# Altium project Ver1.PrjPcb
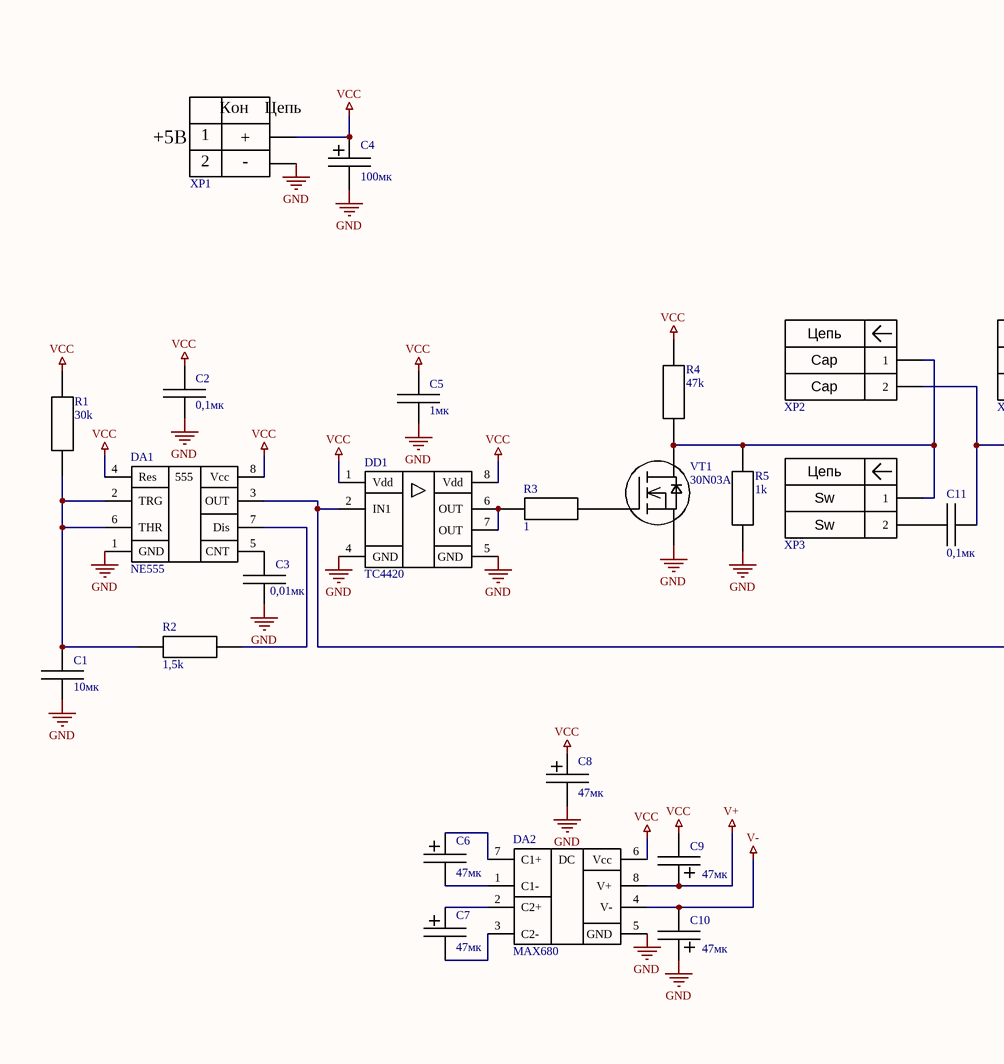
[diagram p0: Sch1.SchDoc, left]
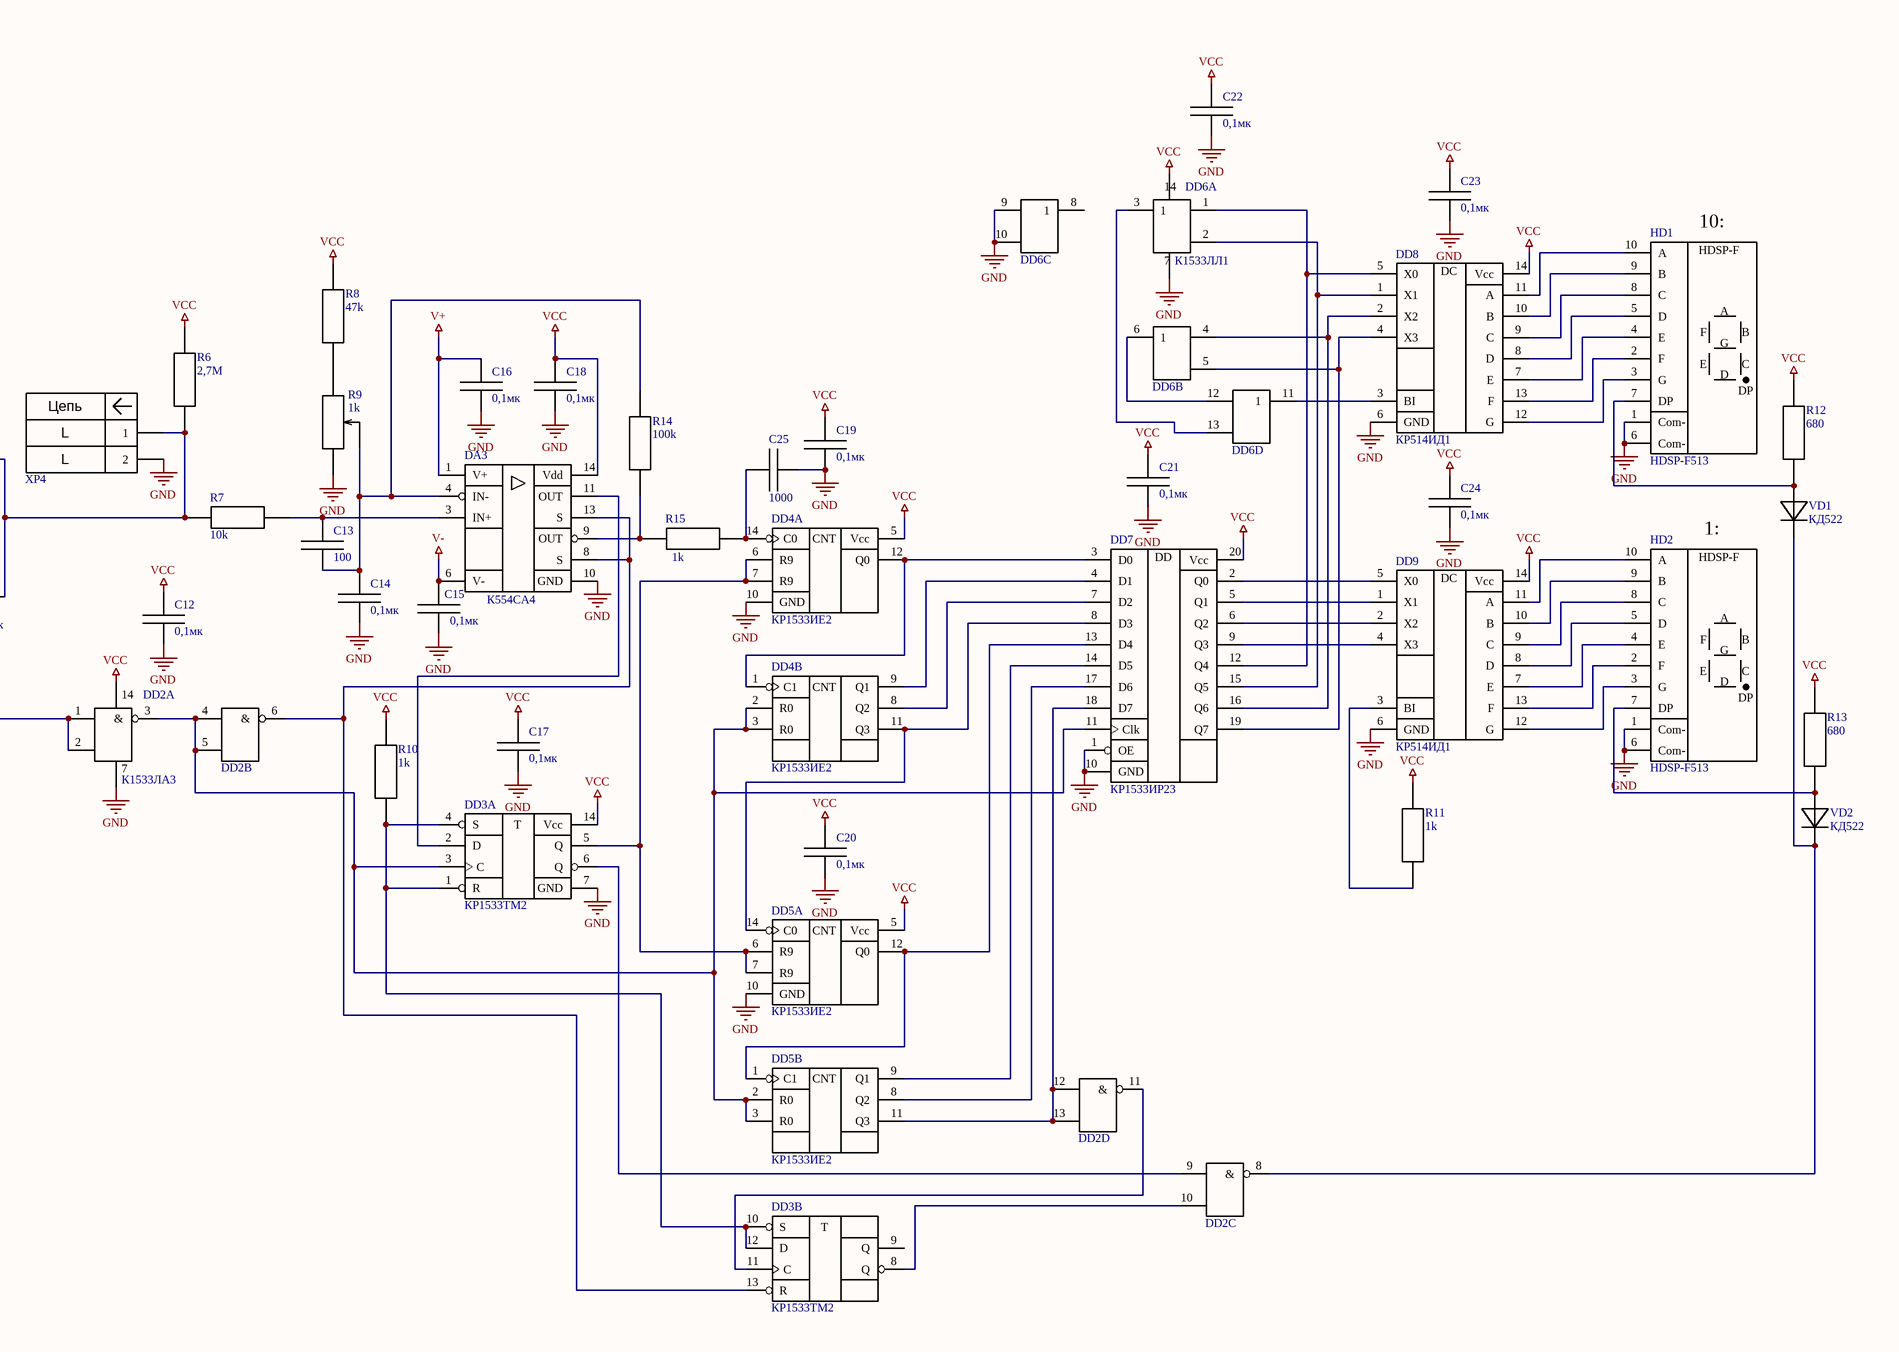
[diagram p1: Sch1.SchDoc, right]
1 sheet, 61 parts. Net scope: global (net labels, ports and power ports of the same name join across sheets).
Board file: PCB1.PcbDoc

## Sheet Sch1.SchDoc: Наименование
size 594 x 420 mm; ApprovedBy: Утвердил; CheckedBy: Проверил; Author: E.J.SanYo; CompanyName: Организация; DocumentNumber: Обозначение; SheetTotal: 1; TechContr: Техн.контр.; NormCotr: Нормоконтроль; DocumentType: Схема электрическая принципиальная; InvNumOrigin: Инв № подл; InvNumDuplicate: Инв № дубл; InsteadOfInvNum: Взам. инв. №; RefNumber: Справ. №; InitialUsage: Перв. примен.; Lit: О

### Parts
C1  value 10мк  [RC_1206]  (hidden comment: C_1206)
C2  value 0,1мк  [RC_1206]  (hidden comment: C_1206)
C3  value 0,01мк  [RC_1206]  (hidden comment: C_1206)
C4  value 100мк  [Type D]  (hidden comment: Type D)
C5  value 1мк  [RC_1206]  (hidden comment: C_1206)
C6  value 47мк  [Type C]  (hidden comment: Type C)
C7  value 47мк  [Type C]  (hidden comment: Type C)
C8  value 47мк  [Type C]  (hidden comment: Type C)
C9  value 47мк  [Type C]  (hidden comment: Type C)
C10  value 47мк  [Type C]  (hidden comment: Type C)
C11  value 0,1мк  [RC_1206]  (hidden comment: C_1206)
C12  value 0,1мк  [RC_1206]  (hidden comment: C_1206)
C13  value 100  [RC_1206]  (hidden comment: C_1206)
C14  value 0,1мк  [RC_1206]  (hidden comment: C_1206)
C15  value 0,1мк  [RC_1206]  (hidden comment: C_1206)
C16  value 0,1мк  [RC_1206]  (hidden comment: C_1206)
C17  value 0,1мк  [RC_1206]  (hidden comment: C_1206)
C18  value 0,1мк  [RC_1206]  (hidden comment: C_1206)
C19  value 0,1мк  [RC_1206]  (hidden comment: C_1206)
C20  value 0,1мк  [RC_1206]  (hidden comment: C_1206)
C21  value 0,1мк  [RC_1206]  (hidden comment: C_1206)
C22  value 0,1мк  [RC_1206]  (hidden comment: C_1206)
C23  value 0,1мк  [RC_1206]  (hidden comment: C_1206)
C24  value 0,1мк  [RC_1206]  (hidden comment: C_1206)
C25  value 1000  [RC_1206]  (hidden comment: C_1206)
DA1  NE555  [DIP-8]
DA2  MAX680  [DIP-8]
DA3  К554СА4  [DIP-14-RU]
DD1  TC4420  [DIP-8]
DD2  К1533ЛА3  [DIP-14-RU]  (parts A,B,C,D of 4)
DD3  КР1533ТМ2  [DIP-14-RU]  (parts A,B of 2)
DD4  КР1533ИЕ2  [DIP-14-RU]  (parts A,B of 2)
DD5  КР1533ИЕ2  [DIP-14-RU]  (parts A,B of 2)
DD6  К1533ЛЛ1  [DIP-14-RU]  (parts A,B,C,D of 4)
DD7  КР1533ИР23  [DIP-20-RU]
DD8  КР514ИД1  [DIP-14-RU]
DD9  КР514ИД1  [DIP-14-RU]
HD1  HDSP-F513  [HDSP-F]
HD2  HDSP-F513  [HDSP-F]
R1  value 30k  [RC_1206]  (hidden comment: R_1206)
R2  value 1,5k  [RC_1206]  (hidden comment: R_1206)
R3  value 1  [RC_1206]  (hidden comment: R_1206)
R4  value 47k  [RC_1206]  (hidden comment: R_1206)
R5  value 1k  [RC_1206]  (hidden comment: R_1206)
R6  value 2,7M  [RC_1206]  (hidden comment: R_1206)
R7  value 10k  [RC_1206]  (hidden comment: R_1206)
R8  value 47k  [RC_1206]  (hidden comment: R_1206)
R9  value 1k  [3296W]  (hidden comment: 3296)
R10  value 1k  [RC_1206]  (hidden comment: R_1206)
R11  value 1k  [RC_1206]  (hidden comment: R_1206)
R12  value 680  [RC_1206]  (hidden comment: R_1206)
R13  value 680  [RC_1206]  (hidden comment: R_1206)
R14  value 100k  [RC_1206]  (hidden comment: R_1206)
R15  value 1k  [RC_1206]  (hidden comment: R_1206)
VD1  КД522  [DO-35]
VD2  КД522  [DO-35]
VT1  30N03A  [TO-252]
XP1  Power  [2EDGV-2P]  (value not drawn)
XP2  Cap  [PLS-2]  (value not drawn)
XP3  Sw  [PLS-2]  (value not drawn)
XP4  Ind  [PLS-2]  (value not drawn)

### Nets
GND: C1.2 C2.2 C3.2 C4.2 C5.2 C8.2 C10.1 C12.2 C14.2 C15.2 C16.2 C17.2 C18.2 C19.2 C20.2 C21.2 C22.2 C23.2 C24.2 C25.2 DA1.1(GND) DA2.5(GND) DA3.10(GND) DD1.4(GND) DD1.5(GND) DD2.7 DD3.7(GND) DD4.10(GND) DD5.10(GND) DD6.7 DD6.9 DD6.10 DD7.1(OE) DD7.10(GND) DD8.6(GND) DD9.6(GND) HD1.1(Com-) HD1.6(Com-) HD2.1(Com-) HD2.6(Com-) R5.1 R9.1 VT1.3(sourse) XP1.2 XP4.2
V+: C9.1 C16.1 DA2.8(V+) DA3.1(V+)
V-: C10.2 C15.1 DA2.4(V-) DA3.6(V-)
VCC: C2.1 C4.1 C5.1 C8.1 C9.2 C12.1 C17.1 C18.1 C19.1 C20.1 C21.1 C22.1 C23.1 C24.1 DA1.4(Res) DA1.8(Vcc) DA2.6(Vcc) DA3.14(Vdd) DD1.1(Vdd) DD1.8(Vdd) DD2.14 DD3.14(Vcc) DD4.5(Vcc) DD5.5(Vcc) DD6.14 DD7.20(Vcc) DD8.14(Vcc) DD9.14(Vcc) R1.2 R4.2 R6.2 R8.2 R10.2 R11.2 R12.2 R13.2 XP1.1
NetC1_1: C1.1 DA1.2(TRG) DA1.6(THR) R1.1 R2.2
NetC3_1: C3.1 DA1.5(CNT)
NetC6_1: C6.1 DA2.7(C1+)
NetC6_2: C6.2 DA2.1(C1-)
NetC7_1: C7.1 DA2.2(C2+)
NetC7_2: C7.2 DA2.3(C2-)
NetC11_1: C11.1 XP3.2
NetC11_2: C11.2 R6.1 R7.2 XP2.2 XP4.1
NetC13_1: C13.1 DA3.3(IN+) R7.1
NetC13_2: C13.2 C14.1 DA3.4(IN-) R9.2 R14.1
NetC25_1: C25.1 DD4.14(C0) R15.1
NetDA1_3: DA1.3(OUT) DD1.2(IN1) DD2.1 DD2.2
NetDA1_7: DA1.7(Dis) R2.1
NetDA3_8: DA3.8(S) DA3.13(S) DD2.6(&) DD3.13(R)
NetDA3_9: DA3.9(OUT) R14.2 R15.2
NetDA3_11: DA3.11(OUT) DD3.2(D)
NetDD1_6: DD1.6(OUT) DD1.7(OUT) R3.2
NetDD2_3: DD2.3(&) DD2.4 DD2.5 DD3.3(C) DD4.2(R0) DD4.3(R0) DD5.2(R0) DD5.3(R0) DD7.11(Clk)
NetDD2_8: DD2.8(&) VD1.2 VD2.2
NetDD2_9: DD2.9 DD3.6(Q)
NetDD2_10: DD2.10 DD3.8(Q)
NetDD2_11: DD2.11(&) DD3.11(C)
NetDD2_12: DD2.12 DD2.13 DD5.11(Q3) DD7.18(D7)
NetDD3_1: DD3.1(R) DD3.4(S) DD3.10(S) DD3.12(D) R10.1
NetDD3_5: DD3.5(Q) DD4.6(R9) DD4.7(R9) DD5.6(R9) DD5.7(R9)
NetDD4_1: DD4.1(C1) DD4.12(Q0) DD7.3(D0)
NetDD4_8: DD4.8(Q2) DD7.7(D2)
NetDD4_9: DD4.9(Q1) DD7.4(D1)
NetDD4_11: DD4.11(Q3) DD5.14(C0) DD7.8(D3)
NetDD5_1: DD5.1(C1) DD5.12(Q0) DD7.13(D4)
NetDD5_8: DD5.8(Q2) DD7.17(D6)
NetDD5_9: DD5.9(Q1) DD7.14(D5)
NetDD6_1: DD6.1 DD7.12(Q4) DD8.5(X0)
NetDD6_2: DD6.2 DD7.15(Q5) DD8.1(X1)
NetDD6_3: DD6.3(1) DD6.13
NetDD6_4: DD6.4 DD7.16(Q6) DD8.2(X2)
NetDD6_5: DD6.5 DD7.19(Q7) DD8.4(X3)
NetDD6_6: DD6.6(1) DD6.12
NetDD6_11: DD6.11(1) DD8.3(BI)
NetDD7_2: DD7.2(Q0) DD9.5(X0)
NetDD7_5: DD7.5(Q1) DD9.1(X1)
NetDD7_6: DD7.6(Q2) DD9.2(X2)
NetDD7_9: DD7.9(Q3) DD9.4(X3)
NetDD8_7: DD8.7(E) HD1.4(E)
NetDD8_8: DD8.8(D) HD1.5(D)
NetDD8_9: DD8.9(C) HD1.8(C)
NetDD8_10: DD8.10(B) HD1.9(B)
NetDD8_11: DD8.11(A) HD1.10(A)
NetDD8_12: DD8.12(G) HD1.3(G)
NetDD8_13: DD8.13(F) HD1.2(F)
NetDD9_3: DD9.3(BI) R11.1
NetDD9_7: DD9.7(E) HD2.4(E)
NetDD9_8: DD9.8(D) HD2.5(D)
NetDD9_9: DD9.9(C) HD2.8(C)
NetDD9_10: DD9.10(B) HD2.9(B)
NetDD9_11: DD9.11(A) HD2.10(A)
NetDD9_12: DD9.12(G) HD2.3(G)
NetDD9_13: DD9.13(F) HD2.2(F)
NetHD1_7: HD1.7(DP) R12.1 VD1.1
NetHD2_7: HD2.7(DP) R13.1 VD2.1
NetR3_1: R3.1 VT1.1(gate)
NetR4_1: R4.1 R5.2 VT1.2(drain) XP2.1 XP3.1
NetR8_1: R8.1 R9.3

Not connected (* = marked no-connect by the designer): DD3 9(Q); DD6 8(1)

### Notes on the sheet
- +5B
- (near HD1) 10:
- 1:
